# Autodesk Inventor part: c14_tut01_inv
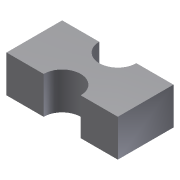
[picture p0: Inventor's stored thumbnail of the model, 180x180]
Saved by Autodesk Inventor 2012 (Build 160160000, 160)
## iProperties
Created: 2010-04
Part Number: c14_tut01_inv
Document SubType Name: Modeling
Designer: CADSoft
Density: 1 g/cm^3
Material: Default
Author: CADSoft
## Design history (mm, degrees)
sketch "Sketch1"
  geometry: L1 (33.666, 15.267)-(33.666, -14.733); L2 (-26.334, -14.733)-(-26.334, 15.267); L3 (-26.334, 15.267)-(-6.334, 15.267); L4 (13.666, 15.267)-(33.666, 15.267); L5 (33.666, -14.733)-(13.666, -14.733); L6 (-6.334, -14.733)-(-26.334, -14.733); A1 r 10 centre (3.666, 15.267) between (-6.334, 15.267) and (13.666, 15.267); A2 r 10 centre (3.666, -14.733) between (13.666, -14.733) and (-6.334, -14.733); 1 further point
  constraints: 12 end point, 5 parallel, 4 equal length, 4 point on circle, 2 centre point, 2 horizontal, 2 horizontal alignment, 2 perpendicular, 1 equal radius
  dimensions: "d0" = 60 distance between parallel lines of L1 L2 (= LEN); "d1" = 30 distance of L2.start L2.end (= WID); "d2" = 10 radius of A1 (= RAD)
extrude "Extrusion1" new body sketch "Sketch1" distance "d3" = 20 (= EXT); taper "d4" = 0 deg
body "Solid1"
other parameters: "LEN" = 60 [user parameter; used in 4 equation terms], "WID" = 30 (= 0.5 x LEN) [user parameter; used in 1 equation term], "RAD" = 10 (= 0.166667 x LEN) [user parameter; used in 1 equation term], "EXT" = 20 (= 0.333333 x LEN) [user parameter; used in 1 equation term]
